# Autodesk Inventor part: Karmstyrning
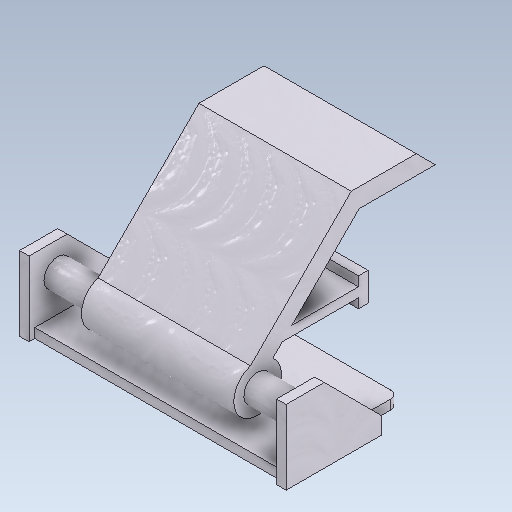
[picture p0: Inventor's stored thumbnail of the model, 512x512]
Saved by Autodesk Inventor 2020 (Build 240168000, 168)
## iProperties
Created: 2019-06
Part Number: Karmstyrning
Material: Aluminum 6061, Welded
Document SubType Name: Modeling
Designer: cl
Density: 2.7 g/cm^3
Appearance: Weld - Aluminum
Author: cl
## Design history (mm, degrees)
sketch "Sketch1"
  geometry: L1 (0, 0)-(0, -50); L2 (0, -50)-(4, -50); L3 (4, -50)-(4, -61); L4 (8, -65)-(122, -65); L5 (126, -61)-(126, -50); L6 (126, -50)-(130, -50); L7 (130, -50)-(130, 0); L8 (130, 0)-(0, 0); A1 r 4 centre (122, -61) between (122, -65) and (126, -61); A2 r 4 centre (8, -61) between (4, -61) and (8, -65); 2 further points
  constraints: 16 end point, 6 point on line, 5 perpendicular, 4 point on circle, 4 tangent, 2 centre point, 1 equal radius, 1 vertical
  dimensions: "d4" = 15 distance of L2.end point (4, -65); "d6" = 15 distance of point (126, -65) L5.end; "d8" = 4 radius of A1; "d14" = 50 distance of L1.start L1.end; "d28" = 130 distance between parallel lines of L7 L1; "d29" = 122 distance of L5.end L2.end; "d32" = 4 distance of L1.end L2.end
extrude "Extrusion1" new body sketch "Sketch1" distance "d9" = 5; taper "d10" = 0 deg
sketch "Sketch4"
  geometry: L1 (0, 0)-(50, 0) reference; L2 (0, 0)-(-3, 0); L3 (-3, 0)-(-3, 39); L4 (17, 39)-(46.414, 9.586); L5 (47, 8.172)-(47, 0); L6 (50, 0)-(61, 0) reference; L7 (0, 0)-(47, 0); L8 (-3, 39)-(17, 39); L9 (-3, 39)-(17, 39); A1 r 2 centre (45, 8.172) between (47, 8.172) and (46.414, 9.586); 1 further point
  constraints: 14 end point, 4 horizontal, 3 point on line, 2 point on circle, 2 tangent, 1 centre point, 1 collinear, 1 perpendicular, 1 vertical
  dimensions: "d15" = 3 distance of L1.start L2.end; "d19" = 9 distance of point (47, 9) L5.end; "d20" = 2 radius of A1 (derived); "d21" = 50 distance from line of L5 L2.end; "d34" = 39 distance of L2.end L3.end; "d35" = 20 distance of L3.end L4.start
extrude "Extrusion2" join sketch "Sketch4" distance "d22" = 5; taper "d23" = 0 deg
sketch "Sketch7"
  geometry: L1 (-3, 39)-(-3, 0) reference; L2 (17, 39)-(-3, 39) reference; C1 r 7.2 at (12, 24); 1 further point
  constraints: 1 centre point
  dimensions: "d39" = 14.4 diameter of C1; "d40" = 15 distance from line of L1 C1.centre; "d41" = 15 distance from line of L2 C1.centre
extrude "Extrusion4" join sketch "Sketch7" distance "d42" = 140; taper "d43" = 0 deg
workplane "Work Plane2"
mirror "Mirror2"
sketch "Sketch8"
  geometry: L1 (33.563, -20.05)-(38.512, -25); L2 (38.512, -25)-(38.512, -65); L3 (38.512, -65)-(33.512, -65); L4 (33.512, -65)-(33.512, -70); L5 (33.512, -70)-(48.512, -70); L6 (48.512, -70)-(48.512, -65); L7 (48.512, -65)-(43.512, -65); L8 (43.512, -65)-(43.512, -30); L9 (43.512, -30)-(78.868, -65.355); L10 (78.868, -65.355)-(78.868, -105.355); L11 (78.868, -105.355)-(88.868, -95.355); L12 (88.868, -95.355)-(88.868, -61.213); L13 (88.868, -61.213)-(35.933, -8.279); L14 (0, -65)-(5, -65) reference; C1 r 7.2 at (24, -12) reference; A1 r 12.5 centre (24, -12) between (35.933, -8.279) and (33.563, -20.05); 1 further point
  constraints: 26 end point, 6 perpendicular, 2 parallel, 2 point on circle, 1 centre point, 1 coincident, 1 collinear, 1 horizontal, 1 vertical
  dimensions: "d74" = 25 diameter of A1; "d75" = 7 distance of L1.start L1.end; "d76" = 40 distance of L1.end L2.end; "d77" = 5 distance of L2.end L3.end; "d78" = 5 distance of L3.end L4.end; "d79" = 15 distance of L4.end L5.end; "d80" = 135 deg angle of L1 L2; "d81" = 5 distance of L6.end L7.end; "d82" = 35 distance of L7.end L8.end; "d83" = 50 distance of L8.end L9.end; "d84" = 45 deg angle of L8 L9; "d85" = 40 distance of L9.end L10.end; "d86" = 45 deg angle of L11 L10; "d87" = 10 distance between parallel lines of L12 L10; "d88" = 5 distance of L5.end L6.end; "d89" = 10 distance between parallel lines of L13 L9
extrude "Extrusion5" join sketch "Sketch8" stored distance "d72" = 80; taper "d73" = 0 deg
body "Solid1"
other parameters: "d44" = -65
